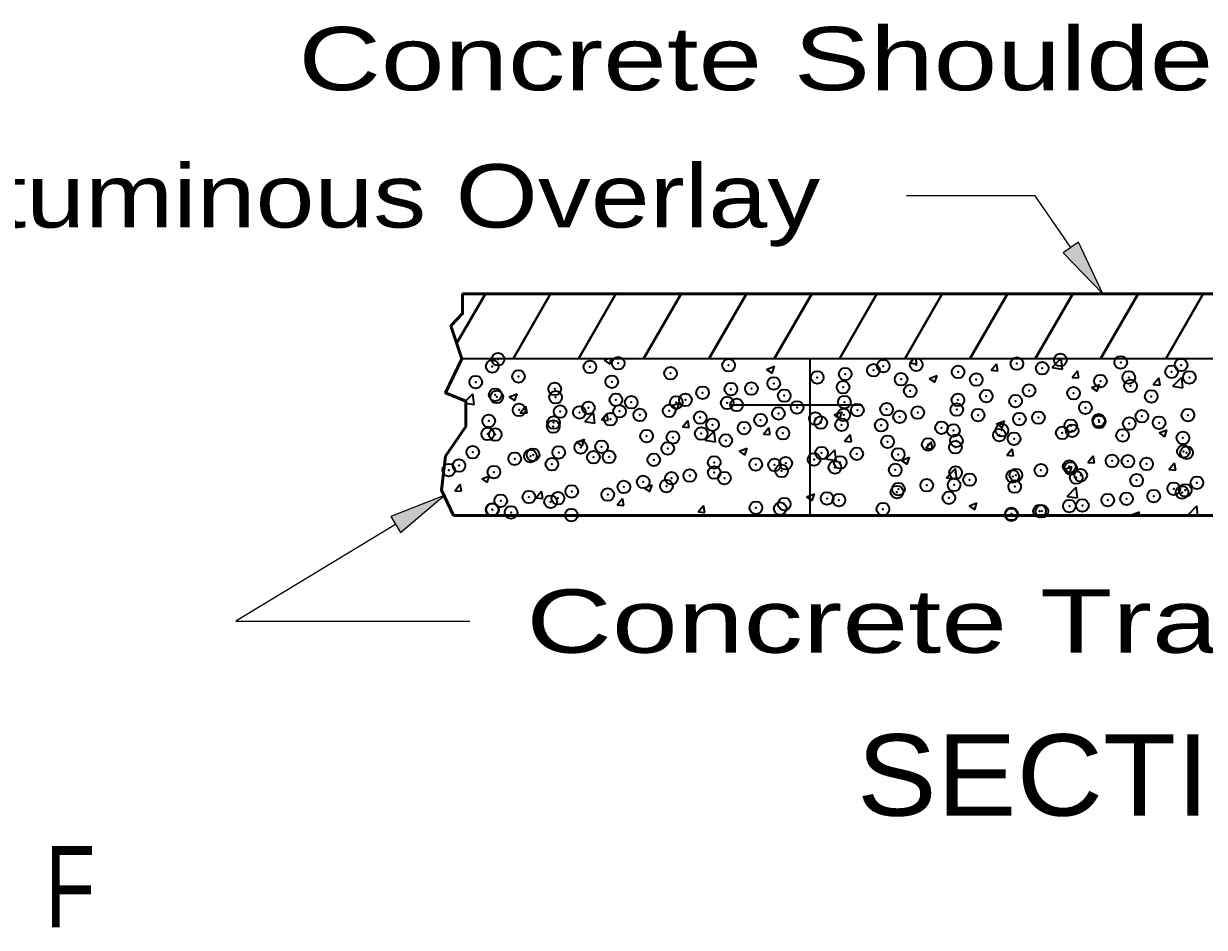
# Model space of a CAD drawing. Extents: x 14 to 49.3, y 28 to 50.
# Drawn here: x 18.004 to 20.615, y 36.951 to 38.95 of the extents above; entities that cross this region are included whole.
import ezdxf

# ---------------------------------------------------------------- set-up
doc = ezdxf.new("R2010")
doc.units = 0
doc.header["$LTSCALE"] = 0.056
doc.header["$PDMODE"] = 32
doc.header["$PDSIZE"] = 0.028
for name, color, linetype, lineweight in [('1', 7, 'Continuous', 35), ('3', 7, 'Continuous', 13), ('5', 7, 'Continuous', 35)]:
    doc.layers.add(name, color=color, linetype=linetype, lineweight=lineweight)

msp = doc.modelspace()

# ---------------------------------------------------------------- hatches: boundary and pattern name
at = {"layer": '3'}
for points in [[(20.33683, 38.467), (20.30267, 38.44325), (20.39083, 38.35233), (20.39083, 38.35233)], [(18.81592, 37.85983), (18.83742, 37.82425), (18.93367, 37.90667), (18.93367, 37.90667)]]:
    msp.add_hatch(color=256, dxfattribs=at).paths.add_polyline_path(points)

# ---------------------------------------------------------------- linework, layer by layer
at = {"layer": '1', "lineweight": 40}
for p, q in [((18.96158, 38.24242), (19.02508, 38.35233)), ((19.08633, 38.20842), (19.16942, 38.35233)), ((19.23067, 38.20842), (19.31375, 38.35233)), ((19.375, 38.20842), (19.45808, 38.35233)), ((19.51933, 38.20842), (19.60242, 38.35233)), ((19.66367, 38.20842), (19.74675, 38.35233)), ((19.808, 38.20842), (19.89108, 38.35233)), ((19.95233, 38.20842), (20.03542, 38.35233)), ((20.09667, 38.20842), (20.17975, 38.35233)), ((20.241, 38.20842), (20.32408, 38.35233)), ((20.38533, 38.20842), (20.46842, 38.35233)), ((20.52967, 38.20842), (20.61275, 38.35233))]:
    msp.add_line(p, q, dxfattribs=at)
at = {"layer": '1', "lineweight": 53}
msp.add_line((22.04675, 38.35233), (18.97467, 38.35233), dxfattribs=at)
at = {"layer": '1'}
for p, q in [((22.02258, 38.20842), (18.97267, 38.20842)), ((19.28775, 38.2055), (19.2955, 38.20842)), ((19.28775, 38.2055), (19.30025, 38.19708)), ((19.30025, 38.19708), (19.304, 38.20842)), ((19.74225, 38.20842), (19.74225, 37.86233)), ((19.96417, 38.19908), (19.972, 38.20842)), ((19.97908, 38.19775), (19.97717, 38.20842)), ((20.27875, 38.18933), (20.29708, 38.20842)), ((20.301, 38.18583), (20.29833, 38.20842)), ((19.64708, 38.18542), (19.66458, 38.19217)), ((19.64708, 38.18542), (19.6595, 38.17708)), ((19.6595, 38.17708), (19.66458, 38.19217)), ((19.96417, 38.19908), (19.97908, 38.19775)), ((20.1435, 38.18333), (20.1555, 38.19775)), ((20.1435, 38.18333), (20.15842, 38.18208)), ((20.15842, 38.18208), (20.1555, 38.19775)), ((20.27875, 38.18933), (20.301, 38.18583)), ((20.32275, 38.16767), (20.33483, 38.182)), ((20.33775, 38.16633), (20.33483, 38.182)), ((20.00633, 38.16542), (20.02383, 38.17217)), ((20.00633, 38.16542), (20.01875, 38.157)), ((20.01875, 38.157), (20.02383, 38.17217)), ((20.32275, 38.16767), (20.33775, 38.16633)), ((20.36567, 38.14542), (20.38317, 38.15208)), ((20.37808, 38.137), (20.38317, 38.15208)), ((20.50208, 38.152), (20.51417, 38.16633)), ((20.50208, 38.152), (20.517, 38.15067)), ((20.51708, 38.15067), (20.51417, 38.16633)), ((20.54558, 38.14792), (20.565, 38.16825)), ((20.56783, 38.1445), (20.565, 38.16825)), ((18.98133, 38.115), (18.99733, 38.13158)), ((19.00008, 38.10783), (18.99733, 38.13158)), ((19.07775, 38.12483), (19.09525, 38.13158)), ((19.07775, 38.12483), (19.09017, 38.11642)), ((19.09017, 38.11642), (19.09525, 38.13158)), ((20.36567, 38.14542), (20.37808, 38.137)), ((20.54558, 38.14792), (20.56775, 38.1445)), ((18.98158, 38.11075), (19.00008, 38.10783)), ((19.10225, 38.08942), (19.11433, 38.10383)), ((19.11725, 38.08817), (19.11433, 38.10383)), ((19.437, 38.10483), (19.4545, 38.1115)), ((19.437, 38.10483), (19.44942, 38.09642)), ((19.44942, 38.09642), (19.4545, 38.1115)), ((19.5655, 38.10725), (19.85742, 38.10725)), ((19.10225, 38.08942), (19.11725, 38.08817)), ((19.24467, 38.06992), (19.26408, 38.09025)), ((19.26692, 38.0665), (19.26417, 38.09025)), ((19.28158, 38.07375), (19.29367, 38.08808)), ((19.28158, 38.07375), (19.2965, 38.07242)), ((19.28158, 38.07375), (19.2965, 38.07242)), ((19.2965, 38.07242), (19.29367, 38.08808)), ((19.46092, 38.05808), (19.47292, 38.07242)), ((19.47583, 38.05675), (19.47292, 38.07242)), ((19.79625, 38.08475), (19.81383, 38.0915)), ((19.79625, 38.08475), (19.80875, 38.07642)), ((19.80875, 38.07642), (19.81383, 38.0915)), ((20.15558, 38.06475), (20.17308, 38.0715)), ((20.168, 38.05642), (20.17308, 38.0715)), ((19.24467, 38.06992), (19.26692, 38.0665)), ((19.46092, 38.05808), (19.47583, 38.05675)), ((19.51142, 38.02858), (19.53092, 38.04883)), ((19.53367, 38.02508), (19.53092, 38.04883)), ((19.64025, 38.04233), (19.65225, 38.05675)), ((19.65517, 38.04108), (19.65225, 38.05675)), ((20.15558, 38.06475), (20.168, 38.05642)), ((20.51483, 38.04475), (20.53233, 38.0515)), ((20.52733, 38.03633), (20.53233, 38.0515)), ((19.22692, 38.02417), (19.24442, 38.03092)), ((19.22692, 38.02417), (19.23942, 38.01583)), ((19.23942, 38.01575), (19.2445, 38.03092)), ((19.51142, 38.02858), (19.53367, 38.02508)), ((19.64025, 38.04233), (19.65517, 38.04108)), ((19.8195, 38.02667), (19.83158, 38.04108)), ((19.8195, 38.02667), (19.8345, 38.02542)), ((19.8345, 38.02533), (19.83158, 38.04108)), ((19.99883, 38.011), (20.01092, 38.02533)), ((20.01375, 38.00967), (20.01092, 38.02533)), ((20.51483, 38.04475), (20.52725, 38.03633)), ((19.58625, 38.00417), (19.60375, 38.01092)), ((19.58625, 38.00417), (19.59867, 37.99575)), ((19.58625, 38.00417), (19.59867, 37.99575)), ((19.59867, 37.99575), (19.60375, 38.01083)), ((19.77825, 37.98717), (19.79775, 38.00742)), ((19.8005, 37.98375), (19.79775, 38.00742)), ((19.99883, 38.011), (20.01375, 38.00967)), ((20.17817, 37.99533), (20.19025, 38.00967)), ((20.17817, 37.99533), (20.19308, 37.994)), ((20.19308, 37.994), (20.19025, 38.00967)), ((20.3575, 37.97958), (20.3695, 37.994)), ((20.37242, 37.97833), (20.3695, 37.994)), ((19.77825, 37.98717), (19.8005, 37.98375)), ((19.9455, 37.98417), (19.963, 37.99083)), ((19.9455, 37.98417), (19.95792, 37.97575)), ((19.958, 37.97575), (19.963, 37.99083)), ((20.30483, 37.96408), (20.32233, 37.97083)), ((20.31725, 37.95575), (20.32233, 37.97083)), ((20.3575, 37.97958), (20.37242, 37.97833)), ((20.53675, 37.96392), (20.54883, 37.97833)), ((20.55175, 37.96258), (20.54883, 37.97825)), ((19.01692, 37.94358), (19.03442, 37.95025)), ((19.01692, 37.94358), (19.02933, 37.93517)), ((19.02933, 37.93517), (19.03442, 37.95025)), ((20.04508, 37.94575), (20.06458, 37.96608)), ((20.04508, 37.94575), (20.06733, 37.94233)), ((20.06733, 37.94233), (20.06458, 37.96608)), ((20.30483, 37.96408), (20.31725, 37.95575)), ((20.53675, 37.96392), (20.55175, 37.96258)), ((18.95767, 37.91708), (18.96967, 37.93142)), ((18.95767, 37.91708), (18.97258, 37.91575)), ((18.97258, 37.91575), (18.96967, 37.93142)), ((19.13692, 37.90142), (19.149, 37.91575)), ((19.15192, 37.90008), (19.149, 37.91575)), ((19.37617, 37.9235), (19.39367, 37.93025)), ((19.37617, 37.9235), (19.38858, 37.91517)), ((19.38858, 37.91517), (19.39367, 37.93025)), ((20.31192, 37.90442), (20.33133, 37.92467)), ((20.33417, 37.90092), (20.33133, 37.92467)), ((19.13692, 37.90142), (19.15192, 37.90008)), ((19.31625, 37.88567), (19.32833, 37.90008)), ((19.33125, 37.88442), (19.32833, 37.90008)), ((19.7355, 37.9035), (19.753, 37.91025)), ((19.7355, 37.9035), (19.74792, 37.89508)), ((19.74792, 37.89508), (19.753, 37.91025)), ((20.09475, 37.8835), (20.11225, 37.89017)), ((20.10717, 37.87508), (20.11225, 37.89017)), ((20.31192, 37.90442), (20.33408, 37.90092)), ((19.31625, 37.88567), (19.33125, 37.88442)), ((19.49558, 37.87), (19.50767, 37.88442)), ((19.49558, 37.87), (19.5105, 37.86867)), ((19.5105, 37.86867), (19.50767, 37.88433)), ((19.68167, 37.86233), (19.68692, 37.86867)), ((19.68817, 37.86233), (19.687, 37.86867)), ((20.09475, 37.8835), (20.10717, 37.87508)), ((20.454, 37.8635), (20.4715, 37.87017)), ((20.454, 37.8635), (20.45567, 37.86233)), ((20.46892, 37.86233), (20.4715, 37.87017)), ((20.57867, 37.863), (20.59817, 37.88333)), ((20.57867, 37.863), (20.58308, 37.86233)), ((20.60058, 37.86233), (20.59817, 37.88333))]:
    msp.add_line(p, q, dxfattribs=at)
at = {"layer": '1', "lineweight": 53}
for points in [[(18.95483, 37.86233), (22.49525, 37.86233), (22.49525, 38.74167), (22.45067, 38.8445), (22.37925, 38.87258), (22.21875, 38.89133), (22.12958, 38.8445), (22.04675, 38.35233)], [(18.97267, 38.20842), (18.94883, 38.28192), (18.97467, 38.309), (18.97467, 38.35233)], [(18.97267, 38.20842), (18.937, 38.13358), (18.98158, 38.11492), (18.98158, 38.05875), (18.937, 37.99333), (18.92808, 37.9185), (18.95483, 37.86233)]]:
    msp.add_lwpolyline(points, dxfattribs=at)
at = {"layer": '1'}
for p in [(19.04042, 38.19183), (19.05308, 38.20775), (19.25617, 38.19067), (19.31875, 38.19892), (19.56292, 38.1945), (19.90492, 38.19283), (19.978, 38.19575), (20.20042, 38.19833), (20.25642, 38.188), (20.29675, 38.20633), (20.43017, 38.20075), (20.56367, 38.19508), (19.09833, 38.16992), (19.4345, 38.17692), (19.75908, 38.16775), (19.82075, 38.17508), (19.88333, 38.18333), (19.94433, 38.16358), (20.07058, 38.17967), (20.11058, 38.16292), (20.44792, 38.16767), (20.54258, 38.18017), (20.58192, 38.1675), (19.00367, 38.15742), (19.17842, 38.14217), (19.30467, 38.15817), (19.56817, 38.14183), (19.61333, 38.14275), (19.66283, 38.15425), (19.816, 38.146), (19.96483, 38.13792), (20.22742, 38.13867), (20.38525, 38.15942), (20.45208, 38.14875), (19.047, 38.12933), (19.05008, 38.1245), (19.18042, 38.12375), (19.31392, 38.11808), (19.34767, 38.11275), (19.44733, 38.11242), (19.4675, 38.11775), (19.50558, 38.13358), (19.55983, 38.11125), (19.68608, 38.12725), (19.819, 38.11292), (20.07017, 38.11792), (20.13275, 38.12617), (20.19742, 38.11517), (20.32575, 38.13275), (20.49767, 38.1255), (19.09967, 38.09575), (19.19042, 38.09208), (19.23317, 38.09017), (19.253, 38.10033), (19.32175, 38.09267), (19.36658, 38.0845), (19.4315, 38.09367), (19.58075, 38.10683), (19.67325, 38.08783), (19.71425, 38.10117), (19.81758, 38.08467), (19.84767, 38.0955), (19.91225, 38.09717), (19.98117, 38.08992), (20.06758, 38.09642), (20.11458, 38.08425), (20.35192, 38.1005), (20.57883, 38.08425), (19.03258, 38.07133), (19.17533, 38.05892), (19.17592, 38.06767), (19.30167, 38.07492), (19.50008, 38.07883), (19.52742, 38.06283), (19.6335, 38.07325), (19.755, 38.0765), (19.76692, 38.06758), (19.81292, 38.06283), (19.90042, 38.06192), (19.94125, 38.08042), (20.20608, 38.07542), (20.24808, 38.07858), (20.3195, 38.06083), (20.3815, 38.073), (20.38208, 38.06908), (20.449, 38.0655), (20.47683, 38.08158), (20.515, 38.06733), (19.03017, 38.04267), (19.047, 38.04133), (19.38167, 38.03783), (19.43983, 38.035), (19.50242, 38.04325), (19.59708, 38.05567), (19.68308, 38.04408), (20.03383, 38.05633), (20.06025, 38.05042), (20.16167, 38.04008), (20.16733, 38.05067), (20.19433, 38.03192), (20.30075, 38.045), (20.32275, 38.0495), (20.43425, 38.03942), (20.56767, 38.03375), (19.23583, 38.01275), (19.28192, 38.01417), (19.42842, 38.01042), (19.55683, 38.02808), (19.9145, 38.02542), (20.00433, 38.01933), (20.0645, 38.01317), (20.06692, 38.02758), (18.99725, 38.00225), (19.09, 37.98775), (19.12467, 37.9935), (19.13067, 37.99667), (19.18725, 38.00175), (19.26417, 37.991), (19.29858, 37.99167), (19.39758, 37.98533), (19.53108, 37.97975), (19.75183, 37.98608), (19.76867, 38.00042), (19.80992, 37.97958), (19.8465, 37.99858), (19.93825, 37.99717), (20.411, 37.98292), (20.446, 37.98233), (20.56892, 38.00375), (20.57583, 38.00108), (18.94425, 37.96275), (18.96675, 37.97267), (19.044, 37.95808), (19.17233, 37.97567), (19.53133, 37.95708), (19.62292, 37.97533), (19.6645, 37.97408), (19.68008, 37.96083), (19.68925, 37.97783), (19.798, 37.96842), (19.93142, 37.96283), (20.06483, 37.95717), (20.25375, 37.96225), (20.31633, 37.9705), (20.31967, 37.96633), (20.48733, 37.97633), (19.37408, 37.93633), (19.42542, 37.92725), (19.43667, 37.94458), (19.47708, 37.95033), (19.55375, 37.94483), (20.00117, 37.929), (20.0615, 37.92992), (20.09583, 37.94142), (20.19133, 37.94867), (20.19833, 37.9515), (20.33175, 37.94592), (20.34158, 37.95133), (20.46525, 37.94025), (20.59867, 37.93458), (19.1215, 37.90308), (19.21617, 37.91558), (19.29558, 37.9085), (19.33133, 37.92533), (19.93525, 37.91392), (19.93858, 37.92075), (20.05, 37.90125), (20.19575, 37.92625), (20.50317, 37.90517), (20.54725, 37.92142), (20.56575, 37.91333), (20.57275, 37.91783), (19.03975, 37.87525), (19.04092, 37.87483), (19.05892, 37.89492), (19.16925, 37.8925), (19.1855, 37.90025), (19.62342, 37.87925), (19.677, 37.87758), (19.686, 37.8875), (19.78075, 37.9), (19.80683, 37.89633), (19.90417, 37.87625), (20.31667, 37.88308), (20.34525, 37.88433), (20.4015, 37.89642), (20.44292, 37.89908), (19.082, 37.86892), (19.21542, 37.86325), (20.188, 37.86367), (20.18833, 37.8655), (20.25058, 37.87192), (20.25567, 37.87142)]:
    msp.add_point(p, dxfattribs=at)
at = {"layer": '3', "lineweight": 25}
for points in [[(20.31975, 38.45517), (20.24092, 38.56925), (19.95667, 38.56925)], [(18.82667, 37.84208), (18.47325, 37.6285), (18.9905, 37.6285)]]:
    msp.add_lwpolyline(points, dxfattribs=at)
at = {"layer": '3'}
for points in [[(20.33683, 38.467), (20.30267, 38.44325), (20.39083, 38.35233), (20.39083, 38.35233)], [(18.81592, 37.85983), (18.83742, 37.82425), (18.93367, 37.90667), (18.93367, 37.90667)]]:
    msp.add_lwpolyline(points, close=True, dxfattribs=at)

# ---------------------------------------------------------------- texts
for s, height, width, p in [('Concrete Shoulder', 0.14, 1.35, (18.61158, 38.80283)), ('2" Bituminous Overlay', 0.14, 1.25, (17.45833, 38.49925)), ('Concrete Transition Pavement', 0.14, 1.4, (19.1155, 37.5585)), ('SECTION F-F', 0.18, 1.1, (19.84658, 37.19817))]:
    msp.add_text(s, height=height, dxfattribs=dict(at, width=width)).set_placement(p)
at = {"layer": '5', "width": 0.75}
msp.add_text('F', height=0.18, dxfattribs=at).set_placement((18.05183, 36.951))

doc.saveas('drawing.dxf')
